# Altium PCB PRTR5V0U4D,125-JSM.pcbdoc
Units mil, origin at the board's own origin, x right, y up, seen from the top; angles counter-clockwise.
Board outline 636.93 x 636.02 mil, 2 copper layers (Top Layer, Bottom Layer), stack 0 mil thick; 1 components, 0 nets, 6 pads, 0 vias.
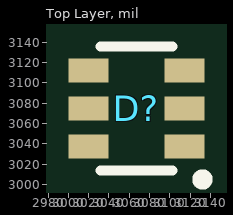
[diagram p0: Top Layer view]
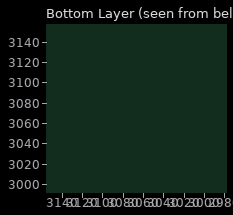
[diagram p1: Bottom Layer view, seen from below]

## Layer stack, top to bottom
Top Layer: signal copper (thickness not stored)
Bottom Layer: signal copper (thickness not stored)

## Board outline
3386.93,2750 2750,2750 2750,3386.02 3386.93,3386.02

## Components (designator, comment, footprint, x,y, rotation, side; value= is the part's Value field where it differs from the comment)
D? "PRTR5V0U4D,125-JSM" SOT-23-6_L2.9-W1.6-P0.95-LS2.8-BR-3 3066.93,3075 r0 top

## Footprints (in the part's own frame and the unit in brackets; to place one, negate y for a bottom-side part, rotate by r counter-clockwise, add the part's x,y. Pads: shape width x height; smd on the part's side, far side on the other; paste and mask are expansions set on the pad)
SOT-23-6_L2.9-W1.6-P0.95-LS2.8-BR-3 [mm]
  rect 1x0.6 smd paste+0 mask+0.051: 1(1.2,-0.95) 2(1.2,0) 3(1.2,0.95) 4(-1.2,0.95) 5(-1.2,0) 6(-1.2,-0.95)
  silkscreen extent -0.9,-1.9 1.78,1.55

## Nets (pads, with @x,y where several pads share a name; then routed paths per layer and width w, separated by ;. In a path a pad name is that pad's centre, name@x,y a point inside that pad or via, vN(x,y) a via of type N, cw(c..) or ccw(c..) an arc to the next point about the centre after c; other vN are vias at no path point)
pads on no net: D?.1 D?.2 D?.3 D?.4 D?.5 D?.6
